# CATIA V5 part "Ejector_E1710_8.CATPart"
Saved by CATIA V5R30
Part number: Vyhazovac_2.5x160_6
Nomenclature: E1710/2.5x160
Description: MEUSBURGER
Property "Material": "1.221"
Publications: "__DrillHole", "Base"
Bounding box of the stored display mesh (mm): x -2.499 to 2.499, y -2.499 to 2.499, z 0 to 152
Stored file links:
  E:\Bakalarka\Model\Forma_v7\Ejector_E1710_8.CATPart
  E:\dev\MoldDesign\intel_a\startup\components\MoldCatalog\Ejector\Meusburger\Ejector_E1710\TableE1710.txt
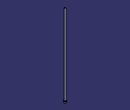
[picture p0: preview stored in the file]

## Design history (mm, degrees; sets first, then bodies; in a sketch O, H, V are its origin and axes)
Parameters
  Ref = "E1710/2.5x160" {design table}
  D1 = 2.5 mm {design table}
  D3 = 5 mm {design table}
  L = 160 mm {design table}
  L3 = 2 mm {design table}
  R = 0.3 mm {design table}
  k_d3 = 6 mm {design table}
  k_d1 = 2.7 mm {design table}
  k_F = 0.3 mm {design table}
  kl = 17 mm {design table}
  Mat = "1.221" {design table}
  HeatTreat = "ISO6751" {design table}
  Offset_Parting = 10 mm
  Anti_Rotation = "Normal"
  Anti_Rotation_D = 1.55 mm
  Anti_Rotation_D_Icut = 1.55 mm
  Add_Length_L = 0.0877 mm
  Add_Length_D3 = 0 mm
  SupplierRef = "Meusburger 2017"
  BmpRef = "F_MldEjectorD1"
  DrillHole_Length = 225 mm
  ValidationTest = false
  Anti_Rotation_D_min = 1.55 mm {= OffSet_D1 /2}
  Anti_Rotation_D_max = 2.425 mm {= D3/2-0.075mm}
  Anti_Rotation_D_ref = 1.55 mm {= Anti_Rotation_D}
  Anti_Rotation_D_Icut_ref = 1.55 mm {= Anti_Rotation_D_Icut}
  Anti_Rotation_Ref_Icut = 2.3246 mm
  Offset_L = 20 mm
  D = 2.5 mm {= D1}
  OffSet_D1 = 3.1 mm {= D1+2*R}
  OffSet_D3 = 6 mm {= D3+1mm}
  XG_Split = 133 mm
  YG_Split = 53.5 mm
  ZG_Split = -198 mm
  DirX_Split = 0 mm
  DirY_Split = 0 mm
  DirZ_Split = 1 mm
Set1 "BaseBody"
  Point1 "Base": (0, 0, 0)
  Plane1: type Offset, RefPlane xy-plane, Offset 225 {= DrillHole_Length}, reversed
  Sketch1 "Sketch.2" on xy-plane, origin (0, 0, 0), H (1, 0, 0), V (0, 1, 0)
    point P1 (-0.46, 1.1623)
    point P2 (0.46, 1.1623)
    construction line L1 (-0.46, 1.1623) -> (0.46, 1.1623)
    point P3 (0.46, -1.1623)
    line L2 (0.46, -1.1623) -> (0.46, 1.1623)
    point P4 (-0.46, -1.1623)
    construction line L3 (0.46, -1.1623) -> (-0.46, -1.1623)
    line L4 (-0.46, 1.1623) -> (-0.46, -1.1623)
    point P5 (-0.21, 1.1623)
    arc A1 centre (-0.21, 1.1623) radius 0.25 from (-0.21, 1.4123) to (-0.46, 1.1623) ccw
    point P7 (0.21, 1.1623)
    point P8 (0.21, 1.4123)
    arc A2 centre (0.21, 1.1623) radius 0.25 from (0.46, 1.1623) to (0.21, 1.4123) ccw
    line L5 (-0.21, 1.4123) -> (0.21, 1.4123)
    point P9 (-0.46, -1.1623)
    arc A3 centre (-0.21, -1.1623) radius 0.25 from (-0.46, -1.1623) to (-0.21, -1.4123) ccw
    point P11 (0.21, -1.4123)
    line L6 (-0.21, -1.4123) -> (0.21, -1.4123)
    point P12 (0.46, -1.1623)
    arc A4 centre (0.21, -1.1623) radius 0.25 from (0.21, -1.4123) to (0.46, -1.1623) ccw
    point P14 (-0.46, 1.1623)
    point P15 (-0.46, -1.1623)
    point P16 (0.46, 1.1623)
    point P17 (0.46, -1.1623)
    reference projected circle E1 centre (0, 0) radius 1.25 from edge [face of Shaft1 from Sketch2.L3 | face of Shaft1 from Sketch2.L4]
    reference projected circle E2 centre (0, 0) radius 1.25 from edge [face of Shaft1 from Sketch2.L3 | face of Shaft1 from Sketch2.L4]
    reference projected circle E3 centre (0, 0) radius 1.25 from edge [face of Shaft1 from Sketch2.L3 | face of Shaft1 from Sketch2.L4]
    reference projected circle E4 centre (0, 0) radius 1.25 from edge [face of Shaft1 from Sketch2.L3 | face of Shaft1 from Sketch2.L4]
    point P18 (-0.46, -1.1623)
    point P19 (-0.21, -1.4123)
    point P20 (0.21, -1.4123)
    point P21 (0.46, -1.1623)
    point P22 (-0.21, -1.4123)
    point P23 (0.21, -1.4123)
    distance P14 P15 = 2.3246 (reference)
    distance P16 P17 = 2.3246 (reference)
    distance L1 P14 = 0 (reference)
    radius A1 = 1.25
    distance L4 V = 1.56
    distance L2 V = 2.435
    distance L5 L6 = 5
    horizontal: L1 H, L3 H, L5 H
    vertical: L2 V, L4 V
    coincidence: P5 L1, P7 L1, P3 P12, P14 L4, P15 L4, P16 L2, P17 L2, P14 E1, P15 E2, P16 E3, P17 E4, P3 P21, P4 P18, P20 P23, P19 P22
    tangency: A1 L4, A2 L2, A2 L5, A1 L5
    symmetry: P1 P9 H, A1 A3 H, P8 P11 H, L5 L6 H, P2 P12 H, A2 A4 H
  DatumSurface1
Body1 "PartBody" (main body)
  Sketch2 "Sketch.1" on zx-plane, origin (0, 0, 0), H (-1, 0, 0), V (0, 0, 1)
    point P1 (0, 160)
    line L1 (1.25, 160) -> (0, 160)
    line L2 (1.25, 2) -> (1.25, 160)
    line L3 (2.5, 2) -> (1.25, 2)
    line L4 (2.5, 0) -> (2.5, 2)
    point P5 (0, 0)
    line L5 (0, 0) -> (2.5, 0)
    point P6 (0, 160)
    axis line L6 (0, 160) -> (0, 0)
    point P7 (0, 0)
    point P8 (1.25, 2)
    point P9 (1.25, 2)
    line L7 (0, 160) -> (0, 0)
    distance L5 L3 = 2 {= L3}
    distance L5 L1 = 160 {= L}
    distance L2 L6 = 1.25 {= D1 /2}
    distance L4 L6 = 2.5 {= D3 /2}
    coincidence: L6 P5, P1 L6, L5 H, L6 V, P7 O, P6 P1, P8 P9
    vertical: L2 V, L7 V
    horizontal: L1 H
  Shaft1 "Shaft.1": profile Sketch2, axis Sketch2.L6, angle 360
  Pocket1 "Pocket.1": profile Sketch1, direction (0, 0, 1), length 3, outer side, deactivated
  Pocket2 "Pocket.2": profile Sketch1, direction (0, 0, 1), length 3, outer side, deactivated
  Fillet1: radius 0.3 {= R}, on edge [face of Shaft1 from Sketch2.L2 | face of Shaft1 from Sketch2.L3]
  Pocket3: profile face of Shaft1 from Sketch2.L1, direction along face of Shaft1 from Sketch2.L1 reversed, up to face of DatumSurface1
Body2 "__DrillHole"
  Sketch3 "Sketch.3" on face of Shaft1, origin (0, 0, 0), H (1, 0, 0), V (0, -1, 0)
    point P1 (0, 0)
    reference projected point E1 (0, 0) from Point1
    coincidence: E1 P1
  Hole1 "Hole.1": placed by Sketch3, at (0, 0, 0) direction (0, 0, 1), diameter 3.1 {= OffSet_D1}, depth 140 {= L-Offset_L}
  Sketch4 "Sketch.4" on face of Shaft1, origin (0, 0, 0), H (1, 0, 0), V (0, -1, 0)
    point P1 (0, 0)
    reference projected point E1 (0, 0) from Point1
    coincidence: E1 P1
  Hole2 "Hole.2": placed by Sketch4, at (0, 0, 0) direction (0, 0, 1), diameter 2.5 {= D1}, depth 160 {= L}
  Sketch5 "Sketch.5" on face of Shaft1 from Sketch2.L3, origin (0, 0, 2), H (1, 0, 0), V (0, 1, 0)
    point P1 (0, 0)
    reference projected point E1 (0, 0) from Point1
    coincidence: E1 P1
  Hole3 "Hole.3": placed by Sketch5, at (0, 0, 2) direction (0, 0, -1), diameter 6 {= OffSet_D3}, depth 227 {= L3 +DrillHole_Length}
  Chamfer1: length 0.3 {= k_F}, angle 45, on edge [face of Hole1 | face of Hole3]
  Body3 "__Body.1"
    Pocket4 "Pocket.3": profile Sketch1, direction (0, 0, -1), length 225, opposite side length 2, deactivated
  Assemble1: tool Body3
  Chamfer2: length 0.3 {= k_F}, angle 45, on edge [start face of Pocket4 | face of Hole1], deactivated
  Body4 "__Body.2"
    Pocket5 "Pocket.4": profile Sketch1, direction (0, 0, -1), length 225, opposite side length 2, deactivated
  Assemble2: tool Body4
  Chamfer3: length 0.3 {= k_F}, angle 45, on edge [start face of Pocket5 | face of Hole1], deactivated
Relations
  design table "TableE1710", configuration 134, drives Ref, D1, D3, L, L3, R, k_d3, k_d1, k_F, kl, Mat, HeatTreat
  Offset_L = 20mm (deactivated)
  rule "Cut_Head_rule":
    let sketch_cut (length)
    let PartBody_Pocket_Sketch (Boolean)
    let I_PartBody_Pocket (Boolean)
    let D_PartBody_Pocket (Boolean)
    let N_DrillHole_Hole (Boolean)
    let N_DrillHole_Hole_Sketch (Boolean)
    let I_DrillHole_Pocket (Boolean)
    let D_DrillHole_Pocket (Boolean)
    /* --------------------------------------------------------------------------------------*/
    if Anti_Rotation =="Normal"
    {
    	sketch_cut=Anti_Rotation_D_max
    	PartBody_Pocket_Sketch = false
    	I_PartBody_Pocket = false
    	D_PartBody_Pocket = false
    	N_DrillHole_Hole = true
    	N_DrillHole_Hole_Sketch = true
    	I_DrillHole_Pocket = false
    	D_DrillHole_Pocket = false
    	Chamfer1.Activity= true
    	Chamfer2.Activity= false
    	Chamfer3.Activity= false
    }
    if Anti_Rotation == "I_Cut"
    {
    	sketch_cut=Anti_Rotation_D_Icut_ref
    	PartBody_Pocket_Sketch = true
    	I_PartBody_Pocket = true
    	D_PartBody_Pocket = false
    	N_DrillHole_Hole = false
    	N_DrillHole_Hole_Sketch = false
    	I_DrillHole_Pocket = true
    	D_DrillHole_Pocket = false
    	Chamfer1.Activity= false
    	Chamfer2.Activity= true
    	Chamfer3.Activity= false
    }
    if Anti_Rotation =="D_Cut"
    {
    	sketch_cut=Anti_Rotation_D_max
    	PartBody_Pocket_Sketch = true
    	I_PartBody_Pocket = false
    	D_PartBody_Pocket = true
    	N_DrillHole_Hole = false
    	N_DrillHole_Hole_Sketch = false
    	I_DrillHole_Pocket = false
    	D_DrillHole_Pocket = true
    	Chamfer1.Activity= false
    	Chamfer2.Activity= false
    	Chamfer3.Activity= true
    }
    /* --------------------------------------------------------------------------------------*/
    Sketch1.distance(L2 V) = sketch_cut+0.01mm
    Sketch1.distance(L4 V) =Anti_Rotation_D_ref+0.01mm
    Sketch1.radius(A1) =D/2
    Pocket4.FirstLimit.Depth = DrillHole_Length
    Pocket5.FirstLimit.Depth = DrillHole_Length
    Pocket1.FirstLimit.Depth = L3+1mm
    Pocket2.FirstLimit.Depth = L3+1mm
    Pocket4.SecondLimit.Depth = L3
    Pocket5.SecondLimit.Depth =L3
    Pocket1.Activity = I_PartBody_Pocket
    Pocket2.Activity = D_PartBody_Pocket
    Sketch1.Activity =PartBody_Pocket_Sketch
    Hole3.Activity= N_DrillHole_Hole
    Sketch5.Activity = N_DrillHole_Hole_Sketch
    Pocket4.Activity = I_DrillHole_Pocket
    Pocket5.Activity  = D_DrillHole_Pocket
  rule "Anti_Rotation_Icut_constrain":
    let Ref1(length)
    let Ref2(length)
    let Ref3(length)
    let Diam1(length)
    let Diam2(length)
    let Add_Length_Lmin (length)
    Ref1=Sketch1.distance(P14 P15)
    Ref2=Sketch1.distance(P16 P17)
    Diam1=D
    Diam2=D3
    /* --------------------------------------------------------------------*/
    if Ref1 >Ref2
    	Anti_Rotation_Ref_Icut = Ref1
    else
    	Anti_Rotation_Ref_Icut  =Ref2
    Add_Length_D3 .InferiorRange=Anti_Rotation_Ref_Icut /2+Diam1/2 -Diam2/2
    if Add_Length_D3 .InferiorRange<0mm
    	Add_Length_D3 .InferiorRange=0mm
    if ValidationTest == "true"
    	Ref3   = 2*Add_Length_L +Anti_Rotation_Ref_Icut  +2*Diam1/2
    else
    	Ref3  =Diam2+2*Add_Length_D3
    if Ref3 <Diam2
    {
    	Ref3 =Diam2
    }
    /* --------------------------------------------------------------------*/
    Sketch1.distance(L5 L6) = Ref3
    Add_Length_L .InferiorRange=Diam2/2-Anti_Rotation_Ref_Icut/2-Diam1/2
    Add_Length_Lmin=Diam2/2-Anti_Rotation_Ref_Icut/2-Diam1/2
    if Add_Length_Lmin<0mm
    	Add_Length_L .InferiorRange=0mm
    else
    	Add_Length_L .InferiorRange=Add_Length_Lmin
